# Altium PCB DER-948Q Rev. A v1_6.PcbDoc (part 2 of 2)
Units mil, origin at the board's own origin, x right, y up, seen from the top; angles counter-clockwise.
Board outline 4950 x 2915 mil, 6 copper layers (Top Layer, Mid-Layer 1, Mid-Layer 2, Mid-Layer 3, Mid-Layer 4, Bottom Layer), stack 69.8 mil thick; 98 components, 37 nets, 247 pads, 846 vias.
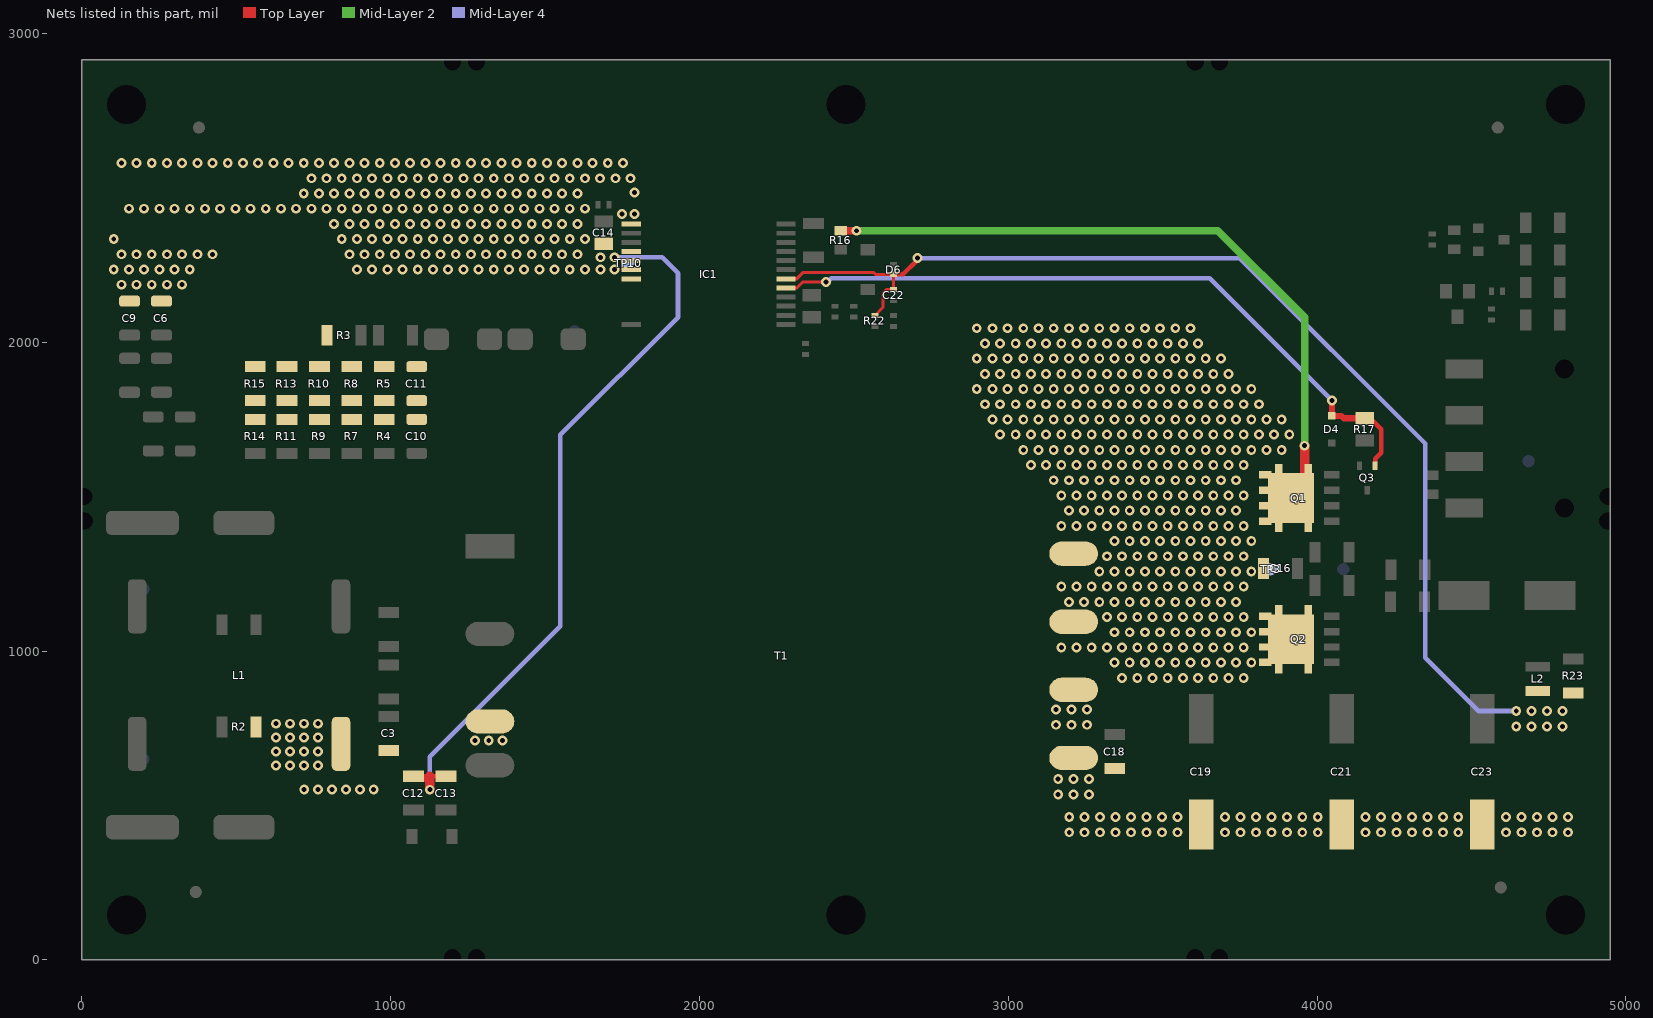
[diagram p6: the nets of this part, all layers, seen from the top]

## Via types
v1: diameter 32, hole 16, Top Layer to Bottom Layer, tented both sides, 845 vias
v2: diameter 32/32/32/32/32/32 (per signal layer), hole 16, Top Layer to Bottom Layer, tented both sides, 1 vias

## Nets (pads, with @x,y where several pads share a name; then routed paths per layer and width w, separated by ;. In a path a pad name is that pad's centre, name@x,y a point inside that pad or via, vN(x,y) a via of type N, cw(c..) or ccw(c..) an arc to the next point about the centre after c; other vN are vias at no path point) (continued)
Q1_D: C16.1 Q1.D Q2.D R16.1 T1.9 T1.10 TP3.1 | length 2446.9
  Top Layer w25: R16.1@2458.18,2361 v1(2508.87,2361)
  Top Layer w30: Q1.D@3876.34,1495.53 Q1.D@3896.02,1515.22 ; Q1.D@3876.34,1534.9 Q1.D@3896.02,1515.22 ; Q1.D@3933.04,1506.15 Q1.D@3974.29,1547.4 ; v1(3960,1665) 3960,1544.53 3955,1539.53 3955,1512.34 Q1.D@3971.81,1495.53 Q1.D@3915.71,1495.53 Q1.D@3896.02,1515.22 ; Q1.D@3965,1502.34 Q1.D@3965,1539.53
  Mid-Layer 2 w25: v1(2508.87,2361) 3679,2361 3960,2080 v1(3960,1665)
  other v1: 3368.9,913.46 3418.11,913.46 3467.32,913.46 3516.54,913.46 3565.75,913.46 3614.96,913.46 3664.17,913.46 3713.39,913.46 3762.6,913.46 3344.29,962.68 3393.5,962.68 3442.72,962.68 3491.93,962.68 3541.14,962.68 3590.35,962.68 3639.57,962.68 3688.78,962.68 3737.99,962.68 3787.2,962.68 3172.05,1011.89 3221.26,1011.89 3270.47,1011.89 3319.68,1011.89 3368.9,1011.89 3418.11,1011.89 3467.32,1011.89 3516.54,1011.89 3565.75,1011.89 3614.96,1011.89 3664.17,1011.89 3713.39,1011.89 3762.6,1011.89 3344.29,1061.1 3393.5,1061.1 3442.72,1061.1 3491.93,1061.1 3541.14,1061.1 3590.35,1061.1 3639.57,1061.1 3688.78,1061.1 3737.99,1061.1 3787.2,1061.1 3319.68,1110.32 3368.9,1110.32 3418.11,1110.32 3467.32,1110.32 3516.54,1110.32 3565.75,1110.32 3614.96,1110.32 3664.17,1110.32 3713.39,1110.32 3762.6,1110.32 3196.65,1159.53 3245.87,1159.53 3295.08,1159.53 3344.29,1159.53 3393.5,1159.53 3442.72,1159.53 3491.93,1159.53 3541.14,1159.53 3590.35,1159.53 3639.57,1159.53 3688.78,1159.53 3737.99,1159.53 3172.05,1208.74 3221.26,1208.74 3270.47,1208.74 3319.68,1208.74 3368.9,1208.74 3418.11,1208.74 3467.32,1208.74 3516.54,1208.74 3565.75,1208.74 3614.96,1208.74 3664.17,1208.74 3713.39,1208.74 3762.6,1208.74 3295.08,1257.95 3344.29,1257.95 3393.5,1257.95 3442.72,1257.95 3491.93,1257.95 3541.14,1257.95 3590.35,1257.95 3639.57,1257.95 3688.78,1257.95 3737.99,1257.95 3787.2,1257.95 3319.68,1307.17 3368.9,1307.17 3418.11,1307.17 3467.32,1307.17 3516.54,1307.17 3565.75,1307.17 3614.96,1307.17 3664.17,1307.17 3713.39,1307.17 3762.6,1307.17 3344.29,1356.38 3393.5,1356.38 3442.72,1356.38 3491.93,1356.38 3541.14,1356.38 3590.35,1356.38 3639.57,1356.38 3688.78,1356.38 3737.99,1356.38 3787.2,1356.38 3172.05,1405.59 3221.26,1405.59 3270.47,1405.59 3319.68,1405.59 3368.9,1405.59 3418.11,1405.59 3467.32,1405.59 3516.54,1405.59 3565.75,1405.59 3614.96,1405.59 3664.17,1405.59 3713.39,1405.59 3762.6,1405.59 3196.65,1454.8 3245.87,1454.8 3295.08,1454.8 3344.29,1454.8 3393.5,1454.8 3442.72,1454.8 3491.93,1454.8 3541.14,1454.8 3590.35,1454.8 3639.57,1454.8 3688.78,1454.8 3737.99,1454.8 3172.05,1504.02 3221.26,1504.02 3270.47,1504.02 3319.68,1504.02 3368.9,1504.02 3418.11,1504.02 3467.32,1504.02 3516.54,1504.02 3565.75,1504.02 3614.96,1504.02 3664.17,1504.02 3713.39,1504.02 3762.6,1504.02 3147.44,1553.23 3196.65,1553.23 3245.87,1553.23 3295.08,1553.23 3344.29,1553.23 3393.5,1553.23 3442.72,1553.23 3491.93,1553.23 3541.14,1553.23 3590.35,1553.23 3639.57,1553.23 3688.78,1553.23 3737.99,1553.23 3073.62,1602.44 3122.83,1602.44 3172.05,1602.44 3221.26,1602.44 3270.47,1602.44 3319.68,1602.44 3368.9,1602.44 3418.11,1602.44 3467.32,1602.44 3516.54,1602.44 3565.75,1602.44 3614.96,1602.44 3664.17,1602.44 3713.39,1602.44 3762.6,1602.44 3049.02,1651.65 3098.23,1651.65 3147.44,1651.65 3196.65,1651.65 3245.87,1651.65 3295.08,1651.65 3344.29,1651.65 3393.5,1651.65 3442.72,1651.65 3491.93,1651.65 3541.14,1651.65 3590.35,1651.65 3639.57,1651.65 3688.78,1651.65 3737.99,1651.65 3787.2,1651.65 3836.42,1651.65 3885.63,1651.65 2973.62,1700.87 3024.41,1700.87 3073.62,1700.87 3122.83,1700.87 3172.05,1700.87 3221.26,1700.87 3270.47,1700.87 3319.68,1700.87 3368.9,1700.87 3418.11,1700.87 3467.32,1700.87 3516.54,1700.87 3565.75,1700.87 3614.96,1700.87 3664.17,1700.87 3713.39,1700.87 3762.6,1700.87 3811.81,1700.87 3861.02,1700.87 3910.24,1700.87 2949.02,1750.08 2998.23,1750.08 3049.02,1750.08 3098.23,1750.08 3147.44,1750.08 3196.65,1750.08 3245.87,1750.08 3295.08,1750.08 3344.29,1750.08 3393.5,1750.08 3442.72,1750.08 3491.93,1750.08 3541.14,1750.08 3590.35,1750.08 3639.57,1750.08 3688.78,1750.08 3737.99,1750.08 3787.2,1750.08 3836.42,1750.08 3885.63,1750.08 2924.41,1799.29 2973.62,1799.29 3024.41,1799.29 3073.62,1799.29 3122.83,1799.29 3172.05,1799.29 3221.26,1799.29 3270.47,1799.29 3319.68,1799.29 3368.9,1799.29 3418.11,1799.29 3467.32,1799.29 3516.54,1799.29 3565.75,1799.29 3614.96,1799.29 3664.17,1799.29 3713.39,1799.29 3762.6,1799.29 3811.81,1799.29 2898.23,1848.5 2949.02,1848.5 2998.23,1848.5 3049.02,1848.5 3098.23,1848.5 3147.44,1848.5 3196.65,1848.5 3245.87,1848.5 3295.08,1848.5 3344.29,1848.5 3393.5,1848.5 3442.72,1848.5 3491.93,1848.5 3541.14,1848.5 3590.35,1848.5 3639.57,1848.5 3688.78,1848.5 3737.99,1848.5 3787.2,1848.5 2924.41,1897.72 2973.62,1897.72 3024.41,1897.72 3073.62,1897.72 3122.83,1897.72 3172.05,1897.72 3221.26,1897.72 3270.47,1897.72 3319.68,1897.72 3368.9,1897.72 3418.11,1897.72 3467.32,1897.72 3516.54,1897.72 3565.75,1897.72 3614.96,1897.72 3664.17,1897.72 3713.39,1897.72 2898.23,1946.93 2949.02,1946.93 2998.23,1946.93 3049.02,1946.93 3098.23,1946.93 3147.44,1946.93 3196.65,1946.93 3245.87,1946.93 3295.08,1946.93 3344.29,1946.93 3393.5,1946.93 3442.72,1946.93 3491.93,1946.93 3541.14,1946.93 3590.35,1946.93 3639.57,1946.93 3688.78,1946.93 2924.41,1996.14 2973.62,1996.14 3024.41,1996.14 3073.62,1996.14 3122.83,1996.14 3172.05,1996.14 3221.26,1996.14 3270.47,1996.14 3319.68,1996.14 3368.9,1996.14 3418.11,1996.14 3467.32,1996.14 3516.54,1996.14 3565.75,1996.14 3614.96,1996.14 2898.23,2045.35 2949.02,2045.35 2998.23,2045.35 3049.02,2045.35 3098.23,2045.35 3147.44,2045.35 3196.65,2045.35 3245.87,2045.35 3295.08,2045.35 3344.29,2045.35 3393.5,2045.35 3442.72,2045.35 3491.93,2045.35 3541.14,2045.35 3590.35,2045.35
SEC_TRF+: C18.1 C19.1 C21.1 C22.1 C23.1 D6.A IC1.6 L2.1 R22.2 R23.1 T1.7 T1.8 | length 3585.8
  Top Layer w10: IC1.6@2280.5,2205.24 2280.83,2205.56 2315.56,2205.56 2336.47,2226.47 2563.53,2226.47 2570.39,2219.61 D6.A@2629.09,2219.61 C22.1@2629.09,2170.67 2605.67,2170.67 2595,2160 2595,2112.91 R22.2@2568.82,2086.73
  Top Layer w15: D6.A@2629.09,2219.61 2659.61,2219.61 2703.75,2263.75 2703.75,2268.9 v1(2707,2272.15)
  Mid-Layer 4 w15: v1(2707,2272.15) 3750.03,2272.15 4350,1672.18 4350,978.97 4523.01,805.96 v1(4644.97,805.96)
  other v1: 3197.73,413.44 3247.73,413.44 3297.73,413.44 3347.73,413.44 3397.73,413.44 3447.73,413.44 3497.73,413.44 3547.73,413.44 3702.27,413.44 3752.27,413.44 3802.27,413.44 3852.27,413.44 3902.27,413.44 3952.27,413.44 4002.27,413.44 4157.27,413.44 4207.27,413.44 4257.27,413.44 4307.27,413.44 4357.27,413.44 4407.27,413.44 4457.27,413.44 4612.27,413.44 4662.27,413.44 4712.27,413.44 4762.27,413.44 4812.27,413.44 3197.73,463.44 3247.73,463.44 3297.73,463.44 3347.73,463.44 3397.73,463.44 3447.73,463.44 3497.73,463.44 3547.73,463.44 3702.27,463.44 3752.27,463.44 3802.27,463.44 3852.27,463.44 3902.27,463.44 3952.27,463.44 4002.27,463.44 4157.27,463.44 4207.27,463.44 4257.27,463.44 4307.27,463.44 4357.27,463.44 4407.27,463.44 4457.27,463.44 4612.27,463.44 4662.27,463.44 4712.27,463.44 4762.27,463.44 4812.27,463.44 3162.06,535.49 3212.06,535.49 3262.06,535.49 3162.06,585.49 3212.06,585.49 3262.06,585.49 4644.97,755.96 4694.97,755.96 4744.97,755.96 4794.97,755.96 3155,761.45 3205,761.45 3255,761.45 4694.97,805.96 4744.97,805.96 4794.97,805.96 3155,811.45 3205,811.45 3255,811.45
SOURCE: C3.2 C6.2 C9.2 C12.2 C13.2 C14.2 IC1.13 IC1.16-19 L1.2 R2.2 T1.5 TP10.1 | length 2401.8
  Top Layer w15: C12.2@1075,595 C12.2@1099.69,595 ; 1110.19,584.5 1101,584.5 1099.69,585.81 C12.2@1099.69,595 ; C13.2@1180,595 1127.52,595 C12.2@1099.69,595
  Top Layer w31.5: v1(1127.52,551.3) 1127.52,595
  Mid-Layer 4 w15: v1(1127.52,551.3) 1127.52,657.52 1550,1080 1550,1700 1931.3,2081.3 1931.3,2223.7 1880,2275 v2(1725,2275)
  other v1: 720.94,551.88 765.94,551.88 810.94,551.88 855.94,551.88 900.94,551.88 945.94,551.88 630,630 675,630 720,630 765,630 630,675 675,675 720,675 765,675 1273.42,710.93 1318.42,710.93 1363.42,710.93 630,720 675,720 720,720 765,720 630,765 675,765 720,765 765,765 128.9,2186.3 178.11,2186.3 227.32,2186.3 276.54,2186.3 325.75,2186.3 1680,2235 1725,2235 104.29,2235.51 153.5,2235.51 202.72,2235.51 251.93,2235.51 301.14,2235.51 350.35,2235.51 891.69,2235.51 940.91,2235.51 990.12,2235.51 1039.33,2235.51 1088.54,2235.51 1137.76,2235.51 1186.97,2235.51 1236.18,2235.51 1285.39,2235.51 1334.61,2235.51 1383.82,2235.51 1433.03,2235.51 1482.24,2235.51 1531.46,2235.51 1580.67,2235.51 1629.88,2235.51 1680,2275 128.9,2284.72 178.11,2284.72 227.32,2284.72 276.54,2284.72 325.75,2284.72 374.96,2284.72 424.17,2284.72 867.09,2284.72 916.3,2284.72 965.51,2284.72 1014.72,2284.72 1063.94,2284.72 1113.15,2284.72 1162.36,2284.72 1211.57,2284.72 1260.79,2284.72 1310,2284.72 1359.21,2284.72 1408.43,2284.72 1457.64,2284.72 1506.85,2284.72 1556.06,2284.72 1605.28,2284.72 104.29,2333.94 842.48,2333.94 891.69,2333.94 940.91,2333.94 990.12,2333.94 1039.33,2333.94 1088.54,2333.94 1137.76,2333.94 1186.97,2333.94 1236.18,2333.94 1285.39,2333.94 1334.61,2333.94 1383.82,2333.94 1433.03,2333.94 1482.24,2333.94 1531.46,2333.94 1580.67,2333.94 1629.88,2333.94 817.87,2383.15 867.09,2383.15 916.3,2383.15 965.51,2383.15 1014.72,2383.15 1063.94,2383.15 1113.15,2383.15 1162.36,2383.15 1211.57,2383.15 1260.79,2383.15 1310,2383.15 1359.21,2383.15 1408.43,2383.15 1457.64,2383.15 1506.85,2383.15 1556.06,2383.15 1605.28,2383.15 1750,2415 1790,2415 153.5,2432.36 202.72,2432.36 251.93,2432.36 301.14,2432.36 350.35,2432.36 399.57,2432.36 448.78,2432.36 497.99,2432.36 547.2,2432.36 596.42,2432.36 645.63,2432.36 694.84,2432.36 744.05,2432.36 793.27,2432.36 842.48,2432.36 891.69,2432.36 940.91,2432.36 990.12,2432.36 1039.33,2432.36 1088.54,2432.36 1137.76,2432.36 1186.97,2432.36 1236.18,2432.36 1285.39,2432.36 1334.61,2432.36 1383.82,2432.36 1433.03,2432.36 1482.24,2432.36 1531.46,2432.36 1580.67,2432.36 1629.88,2432.36 719.45,2481.57 768.66,2481.57 817.87,2481.57 867.09,2481.57 916.3,2481.57 965.51,2481.57 1014.72,2481.57 1063.94,2481.57 1113.15,2481.57 1162.36,2481.57 1211.57,2481.57 1260.79,2481.57 1310,2481.57 1359.21,2481.57 1408.43,2481.57 1457.64,2481.57 1506.85,2481.57 1556.06,2481.57 1605.28,2481.57 1790,2485 744.05,2530.79 793.27,2530.79 842.48,2530.79 891.69,2530.79 940.91,2530.79 990.12,2530.79 1039.33,2530.79 1088.54,2530.79 1137.76,2530.79 1186.97,2530.79 1236.18,2530.79 1285.39,2530.79 1334.61,2530.79 1383.82,2530.79 1433.03,2530.79 1482.24,2530.79 1531.46,2530.79 1580.67,2530.79 1629.88,2530.79 1679.09,2530.79 1728.31,2530.79 1777.52,2530.79 128.9,2580 178.11,2580 227.32,2580 276.54,2580 325.75,2580 374.96,2580 424.17,2580 473.39,2580 522.6,2580 571.81,2580 621.02,2580 670.24,2580 719.45,2580 768.66,2580 817.87,2580 867.09,2580 916.3,2580 965.51,2580 1014.72,2580 1063.94,2580 1113.15,2580 1162.36,2580 1211.57,2580 1260.79,2580 1310,2580 1359.21,2580 1408.43,2580 1457.64,2580 1506.85,2580 1556.06,2580 1605.28,2580 1654.49,2580 1703.7,2580 1752.91,2580
SR: D4.A IC1.5 Q3.G R17.2 | length 2297.7
  Top Layer w10: IC1.5@2280.5,2175.71 2315.71,2175.71 2335,2195 v1(2410,2195)
  Top Layer w15: R17.2@4154.48,1753.67 4172.86,1753.67 4207.96,1718.58 4207.96,1642.58 4188.08,1622.7 Q3.G@4188.08,1599.89
  Top Layer w20: v1(4047.99,1811.69) D4.A@4047.99,1761.67 4079.1,1761.67 4087.1,1753.67 R17.2@4154.48,1753.67
  Mid-Layer 4 w15: v1@2410.94,2195.94 2415.54,2195.94 2426.67,2207.07 3652.62,2207.07 v1(4047.99,1811.69)
VSNUB1: C10.2 C11.1 R4.2 R5.1 R7.2 R8.1 R9.2 R10.1 R11.2 R13.1 R14.2 R15.1
VSNUB2: C11.2 R3.1 R5.2 R8.2 R10.2 R13.2 R15.2
pads on no net: HOLE1.0 HOLE2.0 HOLE3.0 HOLE4.0 HOLE5.0 HOLE6.0 IC1.8 IC1.9 IC1.10 IC1.11 IC1.12 IC1.15 J3. PM1.0 PM2.0 PM3.0 PM4.0 TP1.2 TP2.2 TP3.2 TP4.2 TP5.2 TP6.2 TP7.2 TP8.2 TP9.2 TP10.2

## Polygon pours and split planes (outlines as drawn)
SOURCE on Bottom Layer "SOURCE" (solid, pour order 244): 78.7,2056.3 80,2055 80,1745 130,1695 440,1695 670,1465 670,1365 545.32,1240.32 545.32,1131.62 545.32,658.56 693.52,510.36 750.67,510.36 973.15,510.36 992.03,529.24 992.03,640.9 1118.68,767.55 1118.68,985.68 1118.42,1117.73 1085,1151.15 1085,1523.84 1118.68,1557.52 1118.68,1866.32 1033.42,1951.58 681.81,1951.58 585,2048.4 585,2260 625,2300 795,2300 901,2194 1810.5,2194 1810.5,2574.5 1785,2600 124,2600 78.7,2554.7
NetC16_2 on Bottom Layer "NetC9_2" (solid, pour order 323): 4010.99,1186.05 4010.99,1344.01 4001.5,1353.5 3957.94,1353.5 3919,1314.56 3919,1223.06 3962.83,1179.23 4004.17,1179.23
HV- on Bottom Layer "GND" (solid, pour order 311): 98.07,788.07 78.7,768.7 78.7,381.82 93.46,367.06 307.06,367.06 325,385 325,770 306.93,788.07
"HV+ (1000 V)" on Bottom Layer "GND" (solid, pour order 310): 90.86,1455 78.7,1442.84 78.7,1071.3 98.19,1051.81 306.81,1051.81 325,1070 325,1440 310,1455
"15VCC (-)" on Bottom Layer "NONET_L01_P-001" (solid, pour order 285): 4537.01,1672.01 4537.01,1542.13 4585.85,1493.29 4585.85,1061.56 4537.01,1012.72 4437.28,1012.72 4415,1035 4415,2557.79 4458.21,2601 4651.12,2601 4693.73,2558.39 4693.73,1828.73
Q1_D on Bottom Layer "Q1_D" (solid, pour order 249): 3350,895 3300,945 3165,945 3133.32,976.68 3133.32,1182.44 3133.32,1506.68 2875,1765 2875,2055 2915,2095 3570,2095 3935,1730 3935,1630 3955,1610 3979.58,1610 3990.71,1598.88 3990.71,1392.18 3977.91,1379.38 3947.55,1379.38 3882.7,1314.54 3882.7,1213.66 3947.61,1148.75 3983.62,1148.75 3990.71,1141.66 3990.71,934.97 3950.74,895
GND on Bottom Layer "GND" (solid, pour order 206): 4571.69,660.07 4600.11,688.49 4600.11,941.76 4573.72,968.15 4445.31,968.15 4395,1018.46 4395,2557.68 4351.68,2601 2292.53,2601 2249.4,2557.87 2249.4,1950.6 2275,1925 2650,1925 2845,2120 3580,2120 4022.99,1677.01 4022.99,922.99 3965.63,865.63 3365.63,865.63 3311.47,811.47 3311.47,678.06 3329.46,660.07
"15VCC (+)" on Bottom Layer "NONET_L01_P-001" (solid, pour order 191): 4742.01,2445 4765.9,2468.89 4846.11,2468.89 4870,2445 4870,947.19 4856.43,933.62 4639.98,933.62 4620,953.6 4620,1512.67 4555.54,1577.13 4555.54,1656.1 4742.01,1842.57
SEC_TRF+ on Bottom Layer "Bottom Layer-SEC_TRF+" (solid, pour order 307): 3133.32,396.68 3175,355 4830,355 4870,395 4870,876.5 4856.5,890 4640,890 4620,870 4620,680 4580,640 3321.15,640 3291.4,669.74 3291.4,890.22 3267.73,913.88 3156.38,913.88 3133.32,890.82 3133.32,672.48
SOURCE on Bottom Layer "GND" (solid, pour order 265): 1041.5,579.97 1041.5,613 1048.5,620 1240.02,811.52 1377.97,811.52 1401.03,788.46 1401.03,711.03 1380,690 1250,690 1220,660 1220,583.5 1213.5,577 1044.47,577
NetD2_A on Bottom Layer "GND" (solid, pour order 252): 1266.62,669.79 1243.55,646.73 1243.55,463.55 1204,424 1181.61,424 1181.61,378.39 1205,355 1350,355 1401.03,406.03 1401.03,646.73 1377.97,669.79
GND on Top Layer "Top Layer-GND" (solid, pour order 303): 4535.9,968.15 4573.72,968.15 4600,941.87 4600,688.38 4571.69,660.07 4533.89,660.07 3329.46,660.07 3310,679.53 3310,810 3365.63,865.63 3965.63,865.63 4022.99,922.99 4022.99,1075.33 4084.86,1075.33 4107.44,1097.91 4107.44,1128.41 4084.99,1150.86 4084.99,1346.52 4022.99,1408.52 4022.99,1534.92 4181.24,1534.92 4237.02,1590.7 4237.02,1787.61 4174.96,1848.66 4032,1848.66 4013.15,1829.81 4013.15,1765.39 3993.4,1745.64 3954.36,1745.64 3580,2120 2845,2120 2650,1925 2427.63,1925 2427.63,1959.04 2399.11,1987.56 2332.3,1987.56 2327.95,1991.9 2327.95,2094.5 2334.11,2100.65 2394.11,2100.65 2405.67,2089.09 2511.72,2089.09 2511.72,2054.01 2537.02,2028.71 2648.14,2028.71 2723.25,2103.83 2723.25,2268.29 2594.52,2397.02 2415.52,2397.02 2385.5,2367 2334.11,2367 2334.11,2398.04 2320.71,2411.44 2249.4,2411.44 2249.4,2557.87 2292.53,2601 4351.68,2601 4395,2557.68 4395,2420.42 4343.5,2368.92 4343.5,1931.23 4343.5,1697.06 4302.96,1656.51 4302.96,1505.3 4256.91,1459.25 4256.91,1053.08 4341.83,968.15
SOURCE on Top Layer "NONET_L01_P-001" (solid, pour order 282): 1743.56,2431.5 1758.85,2431.5 1776.97,2449.62 1776.97,2470.99 1760.65,2487.31 1667.02,2487.31 1646.19,2466.48 1646.19,2348.81 1656,2339 1720,2339 1720,2320 1735,2305 1810.5,2305 1810.5,2194 901,2194 795,2300 472.18,2300 287.18,2115 117.08,2115 78.7,2153.38 78.7,2554.7 124,2600 1785,2600 1810.6,2574.4 1810.6,2374.33 1733.93,2374.33 1733.93,2421.88
NetC8_2 on Top Layer "NETC8_2_L01_P297" (solid, pour order 297): 122,2040.93 122,1930 189,1930 189,2040.93
NetC5_2 on Top Layer "NETC5_2_L01_P298" (solid, pour order 298): 225.37,2040.92 225.37,1930.18 292.37,1930.18 292.37,2040.92
NetC4_2 on Top Layer "NETC4_2_L01_P300" (solid, pour order 300): 368.78,1740.4 368.78,1779.5 292.28,1856 239.37,1856 230.37,1847 230.37,1829 239.37,1820 265.65,1820 301.78,1783.87 301.78,1740.4
Dsnub1 on Top Layer "NONET_L01_P-001" (solid, pour order 317): 1386.69,1974.69 1386.39,1975 1290.25,1975 1279.86,1985.39 1279.86,2034.61 1290.53,2045.28 1450.46,2045.28 1460.87,2034.87 1460.87,1985.19 1450.37,1974.69
Dsnub2 on Top Layer "NONET_L01_P-001" (solid, pour order 315): 1061.08,1987.69 1105.56,1987.69 1118.25,1975 1179.75,1975 1190.15,1985.41 1190.15,1998.41 1190.15,2047.59 1179.44,2058.31 1059.79,2058.31 1056.64,2053.86 1054,2051.23 1054,1994.77
VSNUB1 on Top Layer "VSNUB1_L01_P295" (solid, pour order 295): 1100.68,1828.58 1118.68,1810.58 1118.68,1750.85 1099.83,1732 549.31,1732 528.5,1752.81 528.5,1820 537.08,1828.58
NetR3_2 on Top Layer "NONET_L01_P-001" (solid, pour order 314): 981.81,1996.58 981.81,2049.42 972.92,2058.31 894.08,2058.31 887,2051.23 887,1994.77 894.08,1987.69 972.92,1987.69
Q1_D on Top Layer "Q1_D" (solid, pour order 135): 3350,895 3300,945 3165,945 3133.32,976.68 3133.32,1182.44 3133.32,1506.68 2875,1765 2875,2055 2915,2095 3570,2095 3935,1730 3935,1630 3955,1610 3979.58,1610 3990.71,1598.88 3990.71,1392.18 3977.91,1379.38 3947.55,1379.38 3882.7,1314.54 3882.7,1213.66 3947.61,1148.75 3983.62,1148.75 3990.71,1141.66 3990.71,934.97 3950.74,895
HV_TRF on Top Layer "NONET_L01_P-001" (solid, pour order 275): 510.47,1666.4 518.87,1658 1100.68,1658 1118.68,1640 1118.68,1605.42 1118.68,1557.52 1085,1523.84 1085,1151.15 1141.16,1094.99 1377.97,1094.99 1401.03,1071.92 1401.03,1039.31 1377.97,1016.25 1166.1,1016.25 1093.89,1016.11 1015.01,1094.99 898.7,1094.99 855.53,1051.81 552.35,1051.82 547.08,1057.09 547.08,1187.08 720,1360 720,1462.35 642.35,1540 195,1540 185,1550 185,1660 191.4,1666.4
"HV+ (1000 V)" on Top Layer "NONET_L01_P-001" (solid, pour order 276): 473.08,1236.26 612.45,1375.63 623.98,1387.16 623.98,1442.84 611.81,1455 90.86,1455 78.7,1442.84 78.7,1071.3 98.19,1051.81 467.81,1051.82 473.08,1057.09
HV- on Top Layer "NONET_L01_P-001" (solid, pour order 277): 473.08,620.27 578.59,514.76 623.98,469.37 623.98,383.66 607.37,367.06 93.46,367.06 78.7,381.82 78.7,614.83 78.7,768.7 98.07,788.07 467.81,788.07 473.08,782.79
SOURCE on Top Layer "GND" (solid, pour order 196): 1041.5,577 1041.5,579.97 1041.5,613 1048.5,620 1240.02,811.52 1377.97,811.52 1401.03,788.46 1401.03,711.03 1380,690 1250,690 1220,660 1220,583.5 1213.5,577
NetC7_2 on Top Layer "NETC7_2_L01_P299" (solid, pour order 299): 122,1856 122,1823 203.34,1741.66 256.07,1741.66 265.07,1750.66 265.07,1768.66 256.07,1777.66 230.82,1777.66 193.66,1814.82 193.66,1846.07 183.73,1856
NetC2_2 on Top Layer "NONET_L01_P-001" (solid, pour order 280): 961.54,863.05 1028.54,863.05 1028.54,770.56 961.54,770.56
NetC1_2 on Top Layer "NONET_L01_P-001" (solid, pour order 279): 961.54,1029.54 1028.54,1029.54 1028.54,937 961.54,937
SOURCE on Top Layer "NONET_L01_P-001" (solid, pour order 278): 1028.5,696.79 1032.51,692.78 1032.51,664.8 992.03,624.32 992.03,529.24 973.15,510.36 693.52,510.36 545.32,658.56 545.32,781.04 552.35,788.07 860.65,788.07 870,778.71 870,708.71 881.93,696.79
VSNUB2 on Top Layer "NONET_L01_P-001" (solid, pour order 273): 603.5,2005 725.5,2005 778.29,2057.79 806.44,2057.79 813,2051.23 813,1979 853,1939 1109.68,1939 1118.68,1930 1118.68,1920.86 1100.82,1903 541.5,1903 528.5,1916 528.5,1930
"15VCC (-)" on Top Layer "NONET_L01_P-001" (solid, pour order 268): 4434.8,2105.97 4434.8,1975.2 4445,1965 4465,1965 4473.8,1973.8 4473.8,2105.97
"15VCC (-)" on Top Layer "NONET_L01_P-001" (solid, pour order 267): 4424.09,2316.14 4498.07,2316.14 4504.23,2309.99 4539.66,2309.99 4570,2279.65 4570,2225 4550,2205 4450,2205 4424.09,2230.91 4424.09,2285.14
"15VCC (-)" on Top Layer "NONET_L01_P-001" (solid, pour order 255): 4330.91,1500.92 4353.1,1523.11 4556.03,1523.11 4585.85,1493.29 4585.85,1061.56 4537.02,1012.72 4382.13,1012.72 4330.91,1063.94
NetQ4_D on Top Layer "NONET_L01_P-001" (solid, pour order 260): 4693.73,2038.68 4693.73,2420.68 4616.88,2420.68 4586.97,2390.77 4586.97,2128.67 4586.97,2073.49 4621.78,2038.68 4657.73,2038.68
"15VCC (+)" on Top Layer "NONET_L01_P-001" (solid, pour order 256): 4742.01,1877.01 4540.16,1675.16 4368.86,1675.15 4330.91,1637.2 4330.91,1576.3 4353.1,1554.11 4578.56,1554.11 4620,1512.67 4620,953.6 4639.98,933.62 4856.43,933.62 4870,947.19 4870,2445 4846.11,2468.89 4765.9,2468.89 4742.01,2445
DRAIN on Top Layer "Drain" (solid, pour order 169): 1810.6,2065.67 1810.6,2040.6 1770,2000 1710,2000 1588.83,1878.83 1402,1692 1402,1397 1401.03,1396.03 1401.03,1311.24 1389.5,1299.71 1255.08,1299.71 1243.55,1311.24 1243.55,1366.92 1255.19,1378.55 1296.28,1378.55 1320,1402.27 1320,1455 1320,1730 1550.96,1960.96 1550.96,2054.75 1561.88,2065.67
NetC16_2 on Top Layer "NetC9_2" (solid, pour order 179): 4010.99,1186.05 4010.99,1353.5 3957.94,1353.5 3919,1314.56 3919,1223.06 3962.83,1179.23 4004.17,1179.23
SEC_TRF+ on Top Layer "GND" (solid, pour order 136): 3291.4,669.74 3291.4,890.22 3267.73,913.88 3156.38,913.88 3133.32,890.82 3133.32,672.48 3133.32,396.68 3175,355 4830,355 4870,395 4870,876.5 4856.5,890 4640,890 4620,870 4620,680 4580,640 3321.15,640
NetD2_A on Top Layer "GND" (solid, pour order 144): 1266.62,669.79 1243.55,646.73 1243.55,463.55 1204,424 1181.61,424 1181.61,378.39 1205,355 1350,355 1401.03,406.03 1401.03,646.73 1377.97,669.79
NetC16_2 on Mid-Layer 4 "NetC9_2" (solid, pour order 322): 4010.99,1186.05 4010.99,1344.01 4001.5,1353.5 3957.94,1353.5 3919,1314.56 3919,1223.06 3962.83,1179.23 4004.17,1179.23
GND on Mid-Layer 4 "GND" (solid, pour order 257): 3133.32,890.82 3156.38,913.88 3267.74,913.88 3315.99,865.63 3365.63,865.63 3965.63,865.63 4022.99,922.99 4022.99,1677.01 3580,2120 2845,2120 2650,1925 2275,1925 2249.4,1950.6 2249.4,2557.87 2292.53,2601 4351.68,2601 4395,2557.68 4395,1018.46 4445.31,968.15 4830.06,968.15 4870,928.22 4870,395 4830,355 3175,355 3133.32,396.68
SOURCE on Mid-Layer 4 "NONET_L01_P-001" (solid, pour order 292): 124,2600 1785,2600 1810.5,2574.5 1810.5,2194 901,2194 795,2300 472.18,2300 287.17,2115 117.08,2115 78.7,2153.38 78.7,2554.7
"15VCC (-)" on Mid-Layer 4 "NONET_L01_P-001" (solid, pour order 264): 4870,1209.14 4870,1051.44 4811.78,993.22 4456.78,993.22 4415,1035 4415,2557.79 4458.21,2601 4826.81,2601 4870,2557.81
Q1_D on Mid-Layer 4 "Q1_D" (solid, pour order 213): 3350,895 3300,945 3165,945 3133.32,976.68 3133.32,1182.44 3133.32,1506.68 2875,1765 2875,2055 2915,2095 3570,2095 3935,1730 3935,1630 3955,1610 3979.58,1610 3990.71,1598.88 3990.71,1392.18 3977.91,1379.38 3947.55,1379.38 3882.7,1314.54 3882.7,1213.66 3947.61,1148.75 3983.62,1148.75 3990.71,1141.66 3990.71,934.97 3950.74,895
NetD2_A on Mid-Layer 4 "GND" (solid, pour order 243): 1266.62,669.79 1243.55,646.73 1243.55,463.55 1204,424 1181.61,424 1181.61,378.39 1205,355 1350,355 1401.03,406.03 1401.03,646.73 1377.97,669.79
NetC16_2 on Mid-Layer 1 "NetC9_2" (solid, pour order 319): 4010.99,1186.05 4010.99,1344.01 4001.5,1353.5 3957.94,1353.5 3919,1314.56 3919,1223.06 3962.83,1179.23 4004.17,1179.23
NetD2_A on Mid-Layer 1 "GND" (solid, pour order 240): 1266.62,669.79 1243.55,646.73 1243.55,463.55 1204,424 1181.61,424 1181.61,378.39 1205,355 1350,355 1401.03,406.03 1401.03,646.73 1377.97,669.79
SOURCE on Mid-Layer 1 "NONET_L01_P-001" (solid, pour order 289): 1785,2600 1810.5,2574.5 1810.5,2194 901,2194 795,2300 472.17,2300 287.18,2115 117.08,2115 78.7,2153.38 78.7,2554.7 124,2600 1416,2600
"15VCC (+)" on Mid-Layer 1 "NONET_L01_P-001" (solid, pour order 287): 4870,2557.81 4826.81,2601 4458.33,2601 4415,2557.67 4415,2445 4415,1035 4456.78,993.22 4811.78,993.22 4870,1051.44 4870,1209.14
SOURCE on Mid-Layer 1 "GND" (solid, pour order 283): 1266.52,811.52 1239.75,784.75 1239.75,700.25 1250,690 1380,690 1401.03,711.03 1401.03,788.46 1377.97,811.52
Q1_D on Mid-Layer 1 "Q1_D" (solid, pour order 210): 3350,895 3300,945 3165,945 3133.32,976.68 3133.32,1182.44 3133.32,1506.68 2875,1765 2875,2055 2915,2095 3570,2095 3935,1730 3935,1630 3955,1610 3979.58,1610 3990.71,1598.88 3990.71,1392.18 3977.91,1379.38 3947.55,1379.38 3882.7,1314.54 3882.7,1213.66 3947.61,1148.75 3983.62,1148.75 3990.71,1141.66 3990.71,934.97 3950.74,895
GND on Mid-Layer 1 "GND" (solid, pour order 209): 4395,2445 4395,2557.68 4351.68,2601 2292.53,2601 2249.4,2557.87 2249.4,1950.6 2275,1925 2650,1925 2845,2120 3580,2120 4022.99,1677.01 4022.99,922.99 3965.63,865.63 3315.99,865.63 3291.4,890.22 3267.73,913.88 3156.38,913.88 3133.32,890.82 3133.32,396.68 3175,355 4830,355 4870,395 4870,928.22 4830.06,968.15 4445.31,968.15 4395,1018.46
NetC16_2 on Mid-Layer 2 "NetC9_2" (solid, pour order 320): 4010.99,1186.05 4010.99,1344.01 4001.5,1353.5 3957.94,1353.5 3919,1314.56 3919,1223.06 3962.83,1179.23 4004.17,1179.23
SEC_TRF+ on Mid-Layer 2 "Mid-Layer 2-SEC_TRF+" (solid, pour order 309): 4830,355 4870,395 4870,876.5 4856.5,890 4640,890 4620,870 4620,680 4580,640 3321.15,640 3291.4,669.74 3291.4,890.22 3267.73,913.88 3156.38,913.88 3133.32,890.82 3133.32,672.48 3133.32,396.68 3175,355
SOURCE on Mid-Layer 2 "NONET_L01_P-001" (solid, pour order 290): 1785,2600 124,2600 78.7,2554.7 78.7,2153.38 117.08,2115 287.18,2115 472.18,2300 795,2300 901,2194 1810.5,2194 1810.5,2426.78 1810.6,2426.88 1810.6,2574.4
"15VCC (+)" on Mid-Layer 2 "NONET_L01_P-001" (solid, pour order 286): 4870,2445 4846.11,2468.89 4765.9,2468.89 4742.01,2445 4742.01,1842.57 4574.59,1675.15 4555.54,1656.1 4555.54,1577.13 4620,1512.67 4620,953.6 4639.98,933.62 4856.43,933.62 4870,947.19
SOURCE on Mid-Layer 2 "GND" (solid, pour order 284): 1266.52,811.52 1239.75,784.75 1239.75,700.25 1250,690 1380,690 1401.03,711.03 1401.03,788.46 1377.97,811.52
GND on Mid-Layer 2 "GND" (solid, pour order 266): 4395,2445 4395,2557.68 4351.68,2601 2292.53,2601 2249.4,2557.87 2249.4,1950.6 2275,1925 2650,1925 2845,2120 3580,2120 4022.99,1677.01 4022.99,922.99 3965.63,865.63 3365.63,865.63 3311.47,811.47 3311.47,678.06 3329.46,660.07 4571.69,660.07 4600.11,688.49 4600.11,941.76 4573.72,968.15 4445.31,968.15 4395,1018.46
"15VCC (-)" on Mid-Layer 2 "NONET_L01_P-001" (solid, pour order 262): 4693.73,2558.39 4651.12,2601 4458.33,2601 4415,2557.67 4415,2445 4415,1035 4437.28,1012.72 4537.01,1012.72 4585.85,1061.56 4585.85,1493.29 4537.01,1542.13 4537.01,1672.01 4693.73,1828.73
Q1_D on Mid-Layer 2 "Q1_D" (solid, pour order 227): 3350,895 3300,945 3165,945 3133.32,976.68 3133.32,1182.44 3133.32,1506.68 2875,1765 2875,2055 2915,2095 3570,2095 3935,1730 3935,1630 3955,1610 3979.58,1610 3990.71,1598.88 3990.71,1392.18 3977.91,1379.38 3947.55,1379.38 3882.7,1314.54 3882.7,1213.66 3947.61,1148.75 3983.62,1148.75 3990.71,1141.66 3990.71,934.97 3950.74,895
NetD2_A on Mid-Layer 2 "GND" (solid, pour order 246): 1266.62,669.79 1243.55,646.73 1243.55,463.55 1204,424 1181.61,424 1181.61,378.39 1205,355 1350,355 1401.03,406.03 1401.03,646.73 1377.97,669.79
NetC16_2 on Mid-Layer 3 "NetC9_2" (solid, pour order 321): 4010.99,1186.05 4010.99,1344.01 4001.5,1353.5 3957.94,1353.5 3919,1314.56 3919,1223.06 3962.83,1179.23 4004.17,1179.23
SEC_TRF+ on Mid-Layer 3 "Mid-Layer 3-SEC_TRF+" (solid, pour order 308): 3133.32,890.82 3133.32,672.48 3133.32,396.68 3175,355 4830,355 4870,395 4870,876.5 4856.5,890 4640,890 4620,870 4620,680 4580,640 3321.15,640 3291.4,669.74 3291.4,890.22 3267.73,913.88 3156.38,913.88
SOURCE on Mid-Layer 3 "NONET_L01_P-001" (solid, pour order 291): 1416,2600 1785,2600 1810.5,2574.5 1810.5,2194 901,2194 795,2300 472.18,2300 287.18,2115 117.08,2115 78.7,2153.38 78.7,2554.7 124,2600
"15VCC (+)" on Mid-Layer 3 "NONET_L01_P-001" (solid, pour order 288): 4870,2445 4846.11,2468.89 4765.9,2468.89 4742.01,2445 4742.01,1842.57 4555.54,1656.1 4555.54,1577.13 4620,1512.67 4620,953.6 4639.98,933.62 4856.43,933.62 4870,947.19
"15VCC (-)" on Mid-Layer 3 "NONET_L01_P-001" (solid, pour order 263): 4693.73,2558.39 4651.12,2601 4458.21,2601 4415,2557.79 4415.06,2557.73 4415.06,2445.06 4415,2445 4415,1035 4437.28,1012.72 4537.01,1012.72 4585.85,1061.56 4585.85,1493.29 4537.01,1542.13 4537.01,1672.01 4693.73,1828.73
GND on Mid-Layer 3 "GND" (solid, pour order 207): 4395,2557.68 4351.68,2601 2292.53,2601 2249.4,2557.87 2249.4,1950.6 2275,1925 2650,1925 2845,2120 3580,2120 4022.99,1677.01 4022.99,922.99 3965.63,865.63 3365.63,865.63 3311.47,811.47 3311.47,678.06 3329.46,660.07 4571.69,660.07 4600.11,688.49 4600,941.76 4600,941.87 4573.72,968.15 4445.31,968.15 4395,1018.46
Q1_D on Mid-Layer 3 "Q1_D" (solid, pour order 212): 3350,895 3300,945 3165,945 3133.32,976.68 3133.32,1182.44 3133.32,1506.68 2875,1765 2875,2055 2915,2095 3570,2095 3935,1730 3935,1630 3955,1610 3979.58,1610 3990.71,1598.88 3990.71,1392.18 3977.91,1379.38 3947.55,1379.38 3882.7,1314.54 3882.7,1213.66 3947.61,1148.75 3983.62,1148.75 3990.71,1141.66 3990.71,934.97 3950.74,895
SOURCE on Mid-Layer 3 "GND" (solid, pour order 247): 1266.52,811.52 1239.75,784.75 1239.75,700.25 1250,690 1380,690 1401.03,711.03 1401.03,788.46 1377.97,811.52
NetD2_A on Mid-Layer 3 "GND" (solid, pour order 242): 1266.62,669.79 1243.55,646.73 1243.55,463.55 1204,424 1181.61,424 1181.61,378.39 1205,355 1350,355 1401.03,406.03 1401.03,646.73 1377.97,669.79

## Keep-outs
Keep-Out Layer:
  circle w10: c2476.07,2771.51 r137.8
  circle w10: c2475,145 r137.8
  circle w10: c4806.07,2771.51 r137.8
  circle w10: c145,145 r137.8
  circle w10: c4805,145 r137.8
  circle w10: c145,2770 r137.8

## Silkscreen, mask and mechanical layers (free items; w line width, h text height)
Top Overlay:
  drawing of 50 lines, arcs and shapes, not listed
  text "Designed by" at 2930,2450 h100
  text "DER-948Q" at 3800,2445 h118.11
  text "Power Integrations" at 2808.87,2365 h100
  text "PIA-00074" at 2970,2270 h100
  text "PGOOD" at 4218.71,1893.1 h39.37
  text "CHECK" at 4217.27,1743.1 h39.37
  text "(+)" at 4265,1625 h39.37
  text "15V" at 4301.06,1492.54 h39.37 r90
  text "(-)" at 4270,1425 h39.37
  text "1000V" at 793.87,1298.39 h118.11
  text "(-)  VIN  (+)" at 110,725 h39.37 r90
  text "HV" at 1379.74,369.58 h78.74
  text "LV" at 2954.83,369.03 h78.74
Bottom Solder:
  lines w10: 1197.17,1709.68 1197.17,1670.31 1236.54,1670.31 ; 1197.17,1906.54 1197.17,1945.91 1236.54,1945.91 ; 1563.39,1670.31 1602.76,1670.31 1602.76,1709.68 ; 1563.39,1945.91 1602.76,1945.91 1602.76,1906.54
Remark:
  text ".DATE_PRINT" at 40,3445 h70
  text ".TIME_PRINT" at 390,3445 h70
  text ".Pcb_File_Name_No_Path" at 40,3345 h70
  text ".Printout_Name" at 40,3245 h70
  text ".PLOT_FILE_NAME" at 40,3145 h70
  text ".PRINT_SCALE" at 40,3045 h70
  text "Attention: The wires of THT components must not stand out more than 1.0mm !!" at 40,2945 h70
  text "Product:" at -4,-320 h70
  text ".TitleP" at 281,-320 h70
Outline:
  the board outline again, w10
Cutout:
  lines w10: -80.15,-40.18 -80.15,1389.95 ; -80.13,1390.2 cw(c-40.13,1390.2) -0.13,1390.2 ; -80.13,2954.81 -80.13,1524.68 ccw(c-40.13,1524.68) -0.13,1524.68 ; -80.01,-38.14 ccw(c-38.97,-38.14) -38.97,-79.18 1171,-80.15 ; -80,2955 cw(c-40,2955) -40,2995 ; -40,2994.93 1176,2994.93 ; 0,1390.07 0,-0.06 1175.87,-0.06 ; 0,1524.68 0,2914.81 ; 0,2914.93 1173.14,2914.93 ; 744,2106 cw(c744,2128.01) 721.99,2128.01 cw(c744.99,2128.04) 744.99,2151.03 ; 744.24,2105.81 1860.61,2105.81 ccw(c1860.61,2128.31) 1883.11,2128.31 ccw(c1860.61,2128.31) 1860.61,2150.81 1857.97,2150.81 ; 744.24,2150.81 1857.97,2150.81 ; 1160,1179.8 ccw(c1182.53,1179.8) 1182.53,1157.26 ccw(c1182.53,1179.8) 1205.07,1179.8 1205.07,1179.87 cw(c1205.07,1179.94) 1205,1179.94 1205,1492.51 ccw(c1182.5,1492.51) 1182.5,1515.01 ccw(c1182.5,1492.51) 1160,1492.51 1160,1489.87 1160,1179.87 ; 1172.67,-80.06 ccw(c1172.67,-40.06) 1172.67,-0.06 ; 1172.67,2914.93 ccw(c1172.67,2954.93) 1172.67,2994.93 ; 1304.22,-0.2 3594.67,-0.2 ; 1306,2994.8 3578.67,2994.8 ; 1307,-80.2 3580.67,-80.2 ; 1307,2914.77 3578.74,2914.77 ; 1307.16,-80.06 cw(c1307.16,-40.06) 1307.16,-0.06 ; 1307.16,2914.93 cw(c1307.16,2954.93) 1307.16,2994.93 ; 3577.97,-80.12 ccw(c3577.97,-40.12) 3577.97,-0.12 ; 3577.97,2914.88 ccw(c3577.97,2954.88) 3577.97,2994.88 ; 3709.13,2994.88 4991.14,2994.87 ; 3709.26,-0.12 4949.87,-0.12 ; 3711.99,2914.88 4950,2914.88 4950,1524.74 4950.13,1524.74 ccw(c4990.13,1524.74) 5030.13,1524.74 5030.13,2954.88 ; 3712.46,-80.12 cw(c3712.46,-40.12) 3712.46,-0.12 ; 3712.46,2914.88 cw(c3712.46,2954.88) 3712.46,2994.88 ; 3714.13,-80.2 4989.87,-80.2 ; 4950,0 4950,1390.13 ; 4950.13,1390.26 cw(c4990.13,1390.26) 5030.13,1390.26 ; 4990.14,-80.12 ccw(c4990.14,-40.12) 5030.14,-40.12 5030.15,1390.02 ; 4990.14,2994.88 cw(c4990.14,2954.88) 5030.14,2954.88 ; 1857.97,2150.81 ccw(c1857.97,2150.81) 1857.97,2150.81 ; 5030.13,2954.88 5030.14,2954.88 ; 1665,355 1665,1615 2675,1615 2675,355 1665,355
  text "PCB contour and milled cutout" at 3760,3910 h70
Top WEB:
  text ".Print_Date" at 40,3445 h70
Bot WEB:
  text ".Print_Date" at 4451,-181 h70
Route Tool Path:
  lines w25: 746,2139.5 746.07,2139.5 ; 1192.5,1489.87 1192.5,1489.82 ; 1859,2139.5 1858.93,2139.5 ; -12.5,0 ccw(c0,0) 0,-12.5 ; -12.5,0 ccw(c0,0) 0,-12.5 ; -12.5,0 -12.5,2915 ; -12.5,2915 cw(c0,2915) 0,2927.5 ; -12.5,2915 cw(c0,2915) 0,2927.5 ; 0,-12.5 4950,-12.5 ; 0,2927.5 4950,2927.5 ; 745.95,2116.78 cw(c745.99,2104.28) 745.97,2116.78 ; 745.95,2116.78 cw(c745.91,2128.14) 745.95,2139.5 ccw(c746,2152) 746.07,2139.5 ; 745.95,2116.78 745.97,2116.78 ; 745.97,2116.78 1504.95,2119.36 ; 746.07,2139.5 1858.93,2139.5 ; 1172.42,1491.28 ccw(c1182.5,1492.37) 1172.42,1491.25 cw(c1160,1489.87) 1172.5,1489.87 ; 1172.42,1491.28 cw(c1182.5,1492.37) 1192.64,1492.37 cw(c1182.5,1492.37) 1192.58,1491.25 ccw(c1205,1489.87) 1192.5,1489.82 ; 1172.42,1491.28 cw(c1160,1489.87) 1172.5,1489.87 ; 1172.5,1179.83 ccw(c1182.53,1179.8) 1192.57,1179.8 ccw(c1182.53,1179.8) 1192.57,1179.83 ; 1172.5,1179.83 ccw(c1160,1179.87) 1172.5,1179.87 ; 1172.5,1179.83 ccw(c1160,1179.87) 1172.5,1179.87 ; 1172.5,1179.87 1172.5,1489.87 ; 1172.5,1489.87 1172.5,1489.87 ; 1192.5,1199.96 cw(c1205,1200) 1192.5,1200 ; 1192.5,1199.93 cw(c1205,1200) 1192.5,1200 ; 1192.5,1199.96 1192.5,1199.93 ; 1192.5,1199.93 1192.57,1179.86 ; 1192.5,1200 1192.5,1489.82 ; 1192.57,1179.86 ccw(c1205.07,1179.87) 1192.57,1179.83 ; 1192.57,1179.83 ccw(c1205.07,1179.87) 1192.57,1179.83 ; 1192.57,1179.86 1192.57,1179.83 ; 1504.95,2119.36 cw(c1505.02,2106.86) 1505.02,2119.36 ; 1504.95,2119.36 1504.98,2119.36 cw(c1505.02,2106.86) 1505.02,2119.36 ; 1505.02,2119.36 1861.5,2119.36 ccw(c1861.5,2129.5) 1871.63,2129.5 ccw(c1861.5,2129.5) 1860.38,2139.58 cw(c1859,2152) 1858.93,2139.5 ; 4950,-12.5 ccw(c4950,0) 4962.5,0 ; 4950,-12.5 ccw(c4950,0) 4962.5,0 ; 4950,2927.5 cw(c4950,2915) 4962.5,2915 ; 4950,2927.5 cw(c4950,2915) 4962.5,2915 ; 4962.5,0 4962.5,2915 ; 1677.5,367.5 1677.5,1602.5 2662.5,1602.5 2662.5,367.5 1677.5,367.5
Drill Drawing:
  drawing of 555 lines, arcs and shapes, not listed
  text ".LEGEND" at 2430,4650 h70
  text "NOTES: UNLESS OTHERWISE SPECIFIED /  / 1.  THROUGH HOLES ARE PLATED THROUGH. /  /      EXCEPTIONS WILL BE NOTED IN DRILL CHART \"NOTE\". /  / 2.  PLEASE SEE STACKUP DETAILS. /  / 3.  SOLDER PLATE WILL BE RoHS COMPLIANT. /  / 4.  SOLDER MASK LPI (LIQUID PHOTO IMAGEABLE) BOTH SIDES. COLOR GREEN. /  /       SOLDER MASK (REGISTRATION) -0/+0.003 /  / 5.  SILKSCREEN TOP/BOTTOM SIDE. COLOR WHITE.(MIN.WIDTH 0.005\" MAX.WIDTH 0.010\") /  / 6.  FINISH TO BE HASL. (LEAD FREE) /  / 7.  BOARD DIMENTION +/- 0.005\" /  / 8.  DRILL TOLERANCE+/-0.003\" /  / 9.  TRACE WIDTH UNDER 0.010\" +/- 0.002\" /  /        TRACE WIDTH OVER 0.011\" +/- 0.005\" /  / 10.  TRACE SPACE +/- 0.003\" /  / 11.  SLOTS WIDTH & LENGHTH +/- 0.005\" /  / 12.  MATERIAL FR4 COPPER 1oz THICKNESS 0.062\"" at 5299.34,2085.88 h60
  text "Layer" at 5338.51,1982.3 h44.85
  text "Name" at 5649.97,1982.3 h44.85
  text "Material" at 6350,1982.3 h44.85
  text "Thickness" at 7027.62,1982.3 h44.85
  text "Constant" at 7518.42,1982.3 h44.85
  text "Board Layer Stack" at 7949.44,1982.3 h44.85
  text "Top Overlay" at 5649.97,1892.6 h44.85
  text "Top Solder" at 5649.97,1802.9 h44.85
  text "GL 2467 SG-DG" at 6350,1802.9 h44.85
  text "0,39mil" at 7027.62,1802.9 h44.85
  text "3.5" at 7518.42,1802.9 h44.85
  text "1" at 5338.51,1713.2 h44.85
  text "Top Layer" at 5649.97,1713.2 h44.85
  text "1,40mil" at 7027.62,1713.2 h44.85
  text "Dielectric 1" at 5649.97,1623.5 h44.85
  text "Core-R-1566W" at 6350,1623.5 h44.85
  text "14,20mil" at 7027.62,1623.5 h44.85
  text "4.5" at 7518.42,1623.5 h44.85
  text "2" at 5338.51,1533.8 h44.85
  text "Mid-Layer 1" at 5649.97,1533.8 h44.85
  text "1,40mil" at 7027.62,1533.8 h44.85
  text "Dielectric 10" at 5649.97,1444.1 h44.85
  text "PP-106" at 6350,1444.1 h44.85
  text "2,00mil" at 7027.62,1444.1 h44.85
  text "4.1" at 7518.42,1444.1 h44.85
  text "Dielectric 2" at 5649.97,1354.4 h44.85
  text "PP-106" at 6350,1354.4 h44.85
  text "2,00mil" at 7027.62,1354.4 h44.85
  text "4.1" at 7518.42,1354.4 h44.85
  text "3" at 5338.51,1264.7 h44.85
  text "Mid-Layer 2" at 5649.97,1264.7 h44.85
  text "1,40mil" at 7027.62,1264.7 h44.85
  text "Dielectric 3" at 5649.97,1175 h44.85
  text "PP-1080" at 6350,1175 h44.85
  text "2,70mil" at 7027.62,1175 h44.85
  text "4.1" at 7518.42,1175 h44.85
  text "Dielectric 4" at 5649.97,1085.3 h44.85
  text "PP-1080" at 6350,1085.3 h44.85
  text "2,70mil" at 7027.62,1085.3 h44.85
  text "4.1" at 7518.42,1085.3 h44.85
  text "Dielectric 5" at 5649.97,995.6 h44.85
  text "Core-R-1566W" at 6350,995.6 h44.85
  text "14,20mil" at 7027.62,995.6 h44.85
  text "4.7" at 7518.42,995.6 h44.85
  text "Dielectric 11" at 5649.97,905.9 h44.85
  text "PP-1080" at 6350,905.9 h44.85
  text "2,70mil" at 7027.62,905.9 h44.85
  text "4.1" at 7518.42,905.9 h44.85
  text "Dielectric 6" at 5649.97,816.2 h44.85
  text "PP-1080" at 6350,816.2 h44.85
  text "2,70mil" at 7027.62,816.2 h44.85
  text "4.1" at 7518.42,816.2 h44.85
  text "4" at 5338.51,726.5 h44.85
  text "Mid-Layer 3" at 5649.97,726.5 h44.85
  text "1,40mil" at 7027.62,726.5 h44.85
  text "Dielectric 13" at 5649.97,636.8 h44.85
  text "PP-106" at 6350,636.8 h44.85
  text "2,00mil" at 7027.62,636.8 h44.85
  text "4.1" at 7518.42,636.8 h44.85
  text "Dielectric 12" at 5649.97,547.1 h44.85
  text "PP-106" at 6350,547.1 h44.85
  text "2,00mil" at 7027.62,547.1 h44.85
  text "4.1" at 7518.42,547.1 h44.85
  text "5" at 5338.51,457.4 h44.85
  text "Mid-Layer 4" at 5649.97,457.4 h44.85
  text "1,40mil" at 7027.62,457.4 h44.85
  text "Dielectric 7" at 5649.97,367.7 h44.85
  text "Core-R-1566W" at 6350,367.7 h44.85
  text "14,20mil" at 7027.62,367.7 h44.85
  text "4.5" at 7518.42,367.7 h44.85
  text "6" at 5338.51,278 h44.85
  text "Bottom Layer" at 5649.97,278 h44.85
  text "1,40mil" at 7027.62,278 h44.85
  text "Bottom Solder" at 5649.97,188.3 h44.85
  text "GL 2467 SG-DG" at 6350,188.3 h44.85
  text "0,39mil" at 7027.62,188.3 h44.85
  text "3.5" at 7518.42,188.3 h44.85
  text "Bottom Overlay" at 5649.97,98.6 h44.85
Creepage_top:
  lines w133.86: 1595.54,1325 1595.54,1645 1635.54,1685 2000.54,1685

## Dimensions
0,0 to 4950,0 on Dimension
0,0 to 0,2915 on Dimension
